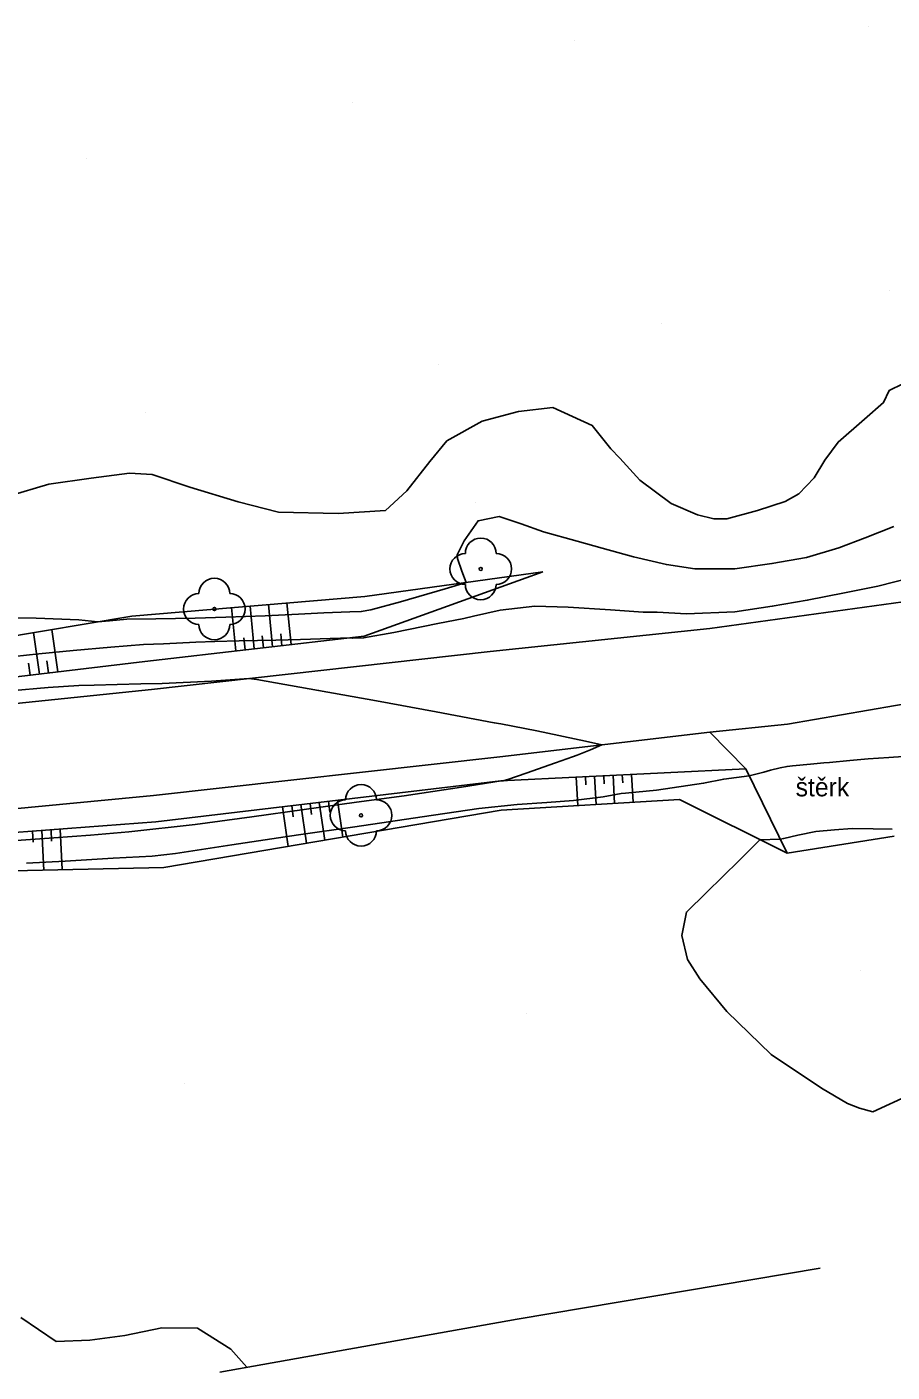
# Model space of a CAD drawing. Extents: x -448957 to -448612, y -1107690 to -1107245.
# Drawn here: x -448841.97 to -448813.9, y -1107413.24 to -1107369.6 of the extents above; entities that cross this region are included whole.
import ezdxf

# ---------------------------------------------------------------- set-up
doc = ezdxf.new("R2010")
doc.units = 0
for name, color, linetype in [('22', 7, 'Continuous'), ('Default', 7, 'Continuous'), ('Vrstva 1', 7, 'Continuous'), ('Vrstva 10', 7, 'Continuous'), ('Vrstva 11', 7, 'Continuous'), ('Vrstva 14', 7, 'Continuous'), ('Vrstva 15', 7, 'Continuous'), ('Vrstva 16', 7, 'Continuous'), ('Vrstva 17', 7, 'Continuous'), ('Vrstva 22', 7, 'Continuous'), ('Vrstva 40', 7, 'Continuous'), ('Vrstva 7', 7, 'Continuous')]:
    doc.layers.add(name, color=color, linetype=linetype)

# ---------------------------------------------------------------- blocks, each defined once
blk = doc.blocks.new('POINT_DISPLAY')
at = {"layer": 'Default'}
blk.add_line((0, 0), (0, 0), dxfattribs=at)
blk = doc.blocks.new('STROM$5')
at = {"layer": '22'}
blk.add_circle((0, 0), 0.5, dxfattribs=at)
for centre, start, end in [((0, 5), 0, 180), ((-5, 0), 90, 270), ((5, 0), 270, 90), ((0, -5), 180, 0)]:
    blk.add_arc(centre, 5, start, end, dxfattribs=at)

msp = doc.modelspace()

# ---------------------------------------------------------------- linework, layer by layer
at = {"layer": 'Vrstva 10'}
for p, q in [((-448819.806, -1107389.115), (-448812.577, -1107388.123)), ((-448826.941, -1107389.864), (-448819.806, -1107389.115)), ((-448837.92, -1107391.094), (-448826.941, -1107389.864)), ((-448845.33, -1107391.868), (-448837.92, -1107391.094)), ((-448817.294, -1107392.217), (-448811.47, -1107391.213)), ((-448826.623, -1107393.28), (-448819.81, -1107392.483)), ((-448819.81, -1107392.483), (-448817.294, -1107392.217)), ((-448837.857, -1107394.533), (-448826.623, -1107393.28)), ((-448845.099, -1107395.225), (-448837.857, -1107394.533))]:
    msp.add_line(p, q, dxfattribs=at)
at = {"layer": 'Vrstva 11'}
for p, q in [((-448819.81, -1107392.483), (-448818.647, -1107393.672)), ((-448818.647, -1107393.672), (-448817.303, -1107396.41)), ((-448817.303, -1107396.41), (-448813.828, -1107395.852))]:
    msp.add_line(p, q, dxfattribs=at)
at = {"layer": 'Vrstva 14'}
for p, q in [((-448831.021, -1107389.369), (-448825.225, -1107387.274)), ((-448831.004, -1107388.073), (-448825.225, -1107387.274)), ((-448838.566, -1107388.715), (-448831.004, -1107388.073)), ((-448845.445, -1107389.871), (-448838.566, -1107388.715)), ((-448838.141, -1107390.183), (-448831.021, -1107389.369)), ((-448845.414, -1107391.056), (-448838.141, -1107390.183)), ((-448826.595, -1107394.055), (-448818.647, -1107393.672)), ((-448837.783, -1107395.389), (-448826.595, -1107394.055)), ((-448826.579, -1107395.014), (-448820.79, -1107394.663)), ((-448820.79, -1107394.663), (-448817.303, -1107396.41)), ((-448837.524, -1107396.869), (-448826.579, -1107395.014)), ((-448845.062, -1107395.942), (-448837.783, -1107395.389)), ((-448845.125, -1107397.033), (-448837.524, -1107396.869))]:
    msp.add_line(p, q, dxfattribs=at)
at = {"layer": 'Vrstva 15'}
for p, q in [((-448835.186, -1107389.845), (-448835.326, -1107388.44)), ((-448834.59, -1107389.777), (-448834.728, -1107388.389)), ((-448833.994, -1107389.709), (-448834.13, -1107388.338)), ((-448833.398, -1107389.641), (-448833.532, -1107388.288)), ((-448841.561, -1107390.594), (-448841.755, -1107389.251)), ((-448840.966, -1107390.522), (-448841.163, -1107389.151)), ((-448834.888, -1107389.811), (-448834.928, -1107389.415)), ((-448834.292, -1107389.743), (-448834.331, -1107389.351)), ((-448833.696, -1107389.675), (-448833.734, -1107389.288)), ((-448841.859, -1107390.629), (-448841.915, -1107390.246)), ((-448841.264, -1107390.558), (-448841.32, -1107390.166)), ((-448823.849, -1107393.923), (-448823.834, -1107394.187)), ((-448823.549, -1107393.908), (-448823.499, -1107394.827)), ((-448823.25, -1107393.894), (-448823.235, -1107394.156)), ((-448822.95, -1107393.879), (-448822.9, -1107394.791)), ((-448822.65, -1107393.865), (-448822.636, -1107394.125)), ((-448822.351, -1107393.85), (-448822.301, -1107394.755)), ((-448824.149, -1107393.937), (-448824.098, -1107394.864)), ((-448832.781, -1107394.793), (-448832.729, -1107395.152)), ((-448832.483, -1107394.757), (-448832.306, -1107395.985)), ((-448832.185, -1107394.721), (-448832.134, -1107395.072)), ((-448831.887, -1107394.686), (-448831.714, -1107395.884)), ((-448833.675, -1107394.899), (-448833.489, -1107396.185)), ((-448833.377, -1107394.864), (-448833.324, -1107395.231)), ((-448833.079, -1107394.828), (-448832.897, -1107396.085)), ((-448841.483, -1107395.67), (-448841.42, -1107396.953)), ((-448841.184, -1107395.647), (-448841.166, -1107396.014)), ((-448840.884, -1107395.625), (-448840.82, -1107396.94)), ((-448841.782, -1107395.693), (-448841.765, -1107396.05))]:
    msp.add_line(p, q, dxfattribs=at)
at = {"layer": 'Vrstva 16'}
for points in [[(-448813.846, -1107385.806), (-448814.768, -1107386.18), (-448815.623, -1107386.497), (-448816.676, -1107386.814), (-448817.798, -1107387.013), (-448819.003, -1107387.181), (-448820.3, -1107387.177), (-448821.22, -1107387.042), (-448822.285, -1107386.788), (-448823.301, -1107386.509), (-448824.114, -1107386.283), (-448825.207, -1107385.977), (-448825.928, -1107385.721), (-448826.64, -1107385.478), (-448827.329, -1107385.621), (-448827.784, -1107386.276), (-448828.013, -1107386.731), (-448827.997, -1107386.85), (-448827.852, -1107387.253), (-448827.718, -1107387.619), (-448828.399, -1107387.832), (-448829.845, -1107388.247), (-448830.81, -1107388.506), (-448831.12, -1107388.566), (-448831.494, -1107388.58), (-448832.329, -1107388.612), (-448833.156, -1107388.654), (-448834.236, -1107388.707), (-448835.515, -1107388.749), (-448836.503, -1107388.776), (-448837.788, -1107388.799), (-448838.728, -1107388.819), (-448839.29, -1107388.867), (-448839.665, -1107388.9), (-448840.287, -1107388.839), (-448841.671, -1107388.786), (-448842.85, -1107388.773)], [(-448813.305, -1107404.233), (-448814.524, -1107404.794), (-448814.959, -1107404.683), (-448815.343, -1107404.526), (-448816.192, -1107404.027), (-448817.821, -1107402.937), (-448819.26, -1107401.541), (-448820.133, -1107400.487), (-448820.54, -1107399.852), (-448820.714, -1107399.079), (-448820.572, -1107398.316), (-448819.921, -1107397.686), (-448818.86, -1107396.644), (-448818.185, -1107395.968), (-448817.526, -1107395.955), (-448817.414, -1107395.928), (-448816.955, -1107395.819), (-448816.376, -1107395.706), (-448815.767, -1107395.645), (-448815.188, -1107395.604), (-448814.509, -1107395.615), (-448813.894, -1107395.624)], [(-448842.163, -1107411.465), (-448841.015, -1107412.25), (-448839.924, -1107412.2), (-448838.786, -1107412.052), (-448837.587, -1107411.81), (-448836.431, -1107411.815), (-448835.355, -1107412.496), (-448834.835, -1107413.085)]]:
    msp.add_lwpolyline(points, dxfattribs=at)
at = {"layer": 'Vrstva 17'}
for points in [[(-448813.55, -1107381.175), (-448813.996, -1107381.396), (-448814.172, -1107381.788), (-448814.791, -1107382.326), (-448815.651, -1107383.066), (-448816.074, -1107383.655), (-448816.42, -1107384.233), (-448816.928, -1107384.743), (-448817.361, -1107384.995), (-448818.269, -1107385.292), (-448819.257, -1107385.563), (-448819.676, -1107385.561), (-448820.21, -1107385.431), (-448821.068, -1107385.064), (-448822.081, -1107384.301), (-448822.734, -1107383.592), (-448823.018, -1107383.287), (-448823.623, -1107382.531), (-448824.905, -1107381.944), (-448826.018, -1107382.08), (-448827.199, -1107382.388), (-448828.343, -1107383.023), (-448828.897, -1107383.703), (-448829.637, -1107384.648), (-448830.338, -1107385.287), (-448831.87, -1107385.381), (-448833.803, -1107385.347), (-448835.108, -1107385.01), (-448836.682, -1107384.534), (-448837.906, -1107384.12), (-448838.643, -1107384.073), (-448839.885, -1107384.236), (-448841.252, -1107384.438), (-448842.561, -1107384.824)], [(-448813.295, -1107387.468), (-448814.359, -1107387.741), (-448815.439, -1107387.957), (-448816.651, -1107388.202), (-448817.787, -1107388.395), (-448818.994, -1107388.575), (-448820.568, -1107388.639), (-448821.523, -1107388.589), (-448821.971, -1107388.582), (-448823.032, -1107388.513), (-448824.407, -1107388.429), (-448825.486, -1107388.388), (-448826.612, -1107388.522), (-448827.475, -1107388.717), (-448827.792, -1107388.789), (-448828.638, -1107388.958), (-448830.066, -1107389.251), (-448831.042, -1107389.423), (-448831.398, -1107389.433), (-448831.471, -1107389.42), (-448832.127, -1107389.44), (-448833.088, -1107389.471), (-448833.893, -1107389.494), (-448835.079, -1107389.519), (-448835.868, -1107389.538), (-448836.488, -1107389.564), (-448837.539, -1107389.609), (-448838.187, -1107389.636), (-448839.241, -1107389.722), (-448840.465, -1107389.829), (-448841.581, -1107389.942), (-448842.777, -1107390.066)], [(-448826.519, -1107394.054), (-448826.479, -1107394.049), (-448826.361, -1107394.011), (-448825.766, -1107393.808), (-448824.814, -1107393.479), (-448824.263, -1107393.285), (-448824.115, -1107393.229), (-448823.678, -1107393.048), (-448823.311, -1107392.893), (-448823.849, -1107392.769), (-448825.427, -1107392.441), (-448826.596, -1107392.213), (-448826.804, -1107392.174), (-448828.685, -1107391.824), (-448830.622, -1107391.465), (-448832.502, -1107391.126), (-448834.51, -1107390.776), (-448834.772, -1107390.741), (-448835.983, -1107390.827), (-448837.582, -1107390.901), (-448838.275, -1107390.909), (-448839.038, -1107390.938), (-448839.789, -1107390.953), (-448840.283, -1107390.964), (-448841.273, -1107391.036), (-448842.505, -1107391.144)], [(-448841.981, -1107396.735), (-448840.722, -1107396.66), (-448839.165, -1107396.567), (-448837.906, -1107396.499), (-448837.145, -1107396.415), (-448835.316, -1107396.136), (-448833.156, -1107395.815), (-448831.324, -1107395.552), (-448829.147, -1107395.231), (-448827.304, -1107394.96), (-448826.064, -1107394.83), (-448825.1, -1107394.762), (-448824.235, -1107394.693), (-448823.271, -1107394.573), (-448822.683, -1107394.475), (-448822.542, -1107394.458), (-448821.545, -1107394.36), (-448820.011, -1107394.138), (-448819.36, -1107394), (-448818.943, -1107393.949), (-448818.535, -1107393.9), (-448818.366, -1107393.857), (-448818.062, -1107393.776), (-448817.837, -1107393.713), (-448817.527, -1107393.642), (-448817.302, -1107393.593), (-448817.123, -1107393.575), (-448816.544, -1107393.52), (-448816.115, -1107393.48), (-448815.925, -1107393.464), (-448815.267, -1107393.402), (-448814.677, -1107393.348), (-448814.004, -1107393.302), (-448813.221, -1107393.245)], [(-448842.31, -1107395.997), (-448841.097, -1107395.909), (-448839.9, -1107395.82), (-448838.656, -1107395.715), (-448836.513, -1107395.473), (-448834.669, -1107395.224), (-448831.277, -1107394.756), (-448829.731, -1107394.544), (-448827.868, -1107394.262), (-448826.577, -1107394.061), (-448826.519, -1107394.054)]]:
    msp.add_lwpolyline(points, dxfattribs=at)
at = {"layer": 'Vrstva 7'}
for p, q in [((-448826.056, -1107411.525), (-448816.229, -1107409.874)), ((-448835.712, -1107413.241), (-448826.056, -1107411.525))]:
    msp.add_line(p, q, dxfattribs=at)

# ---------------------------------------------------------------- block references
at = {"layer": 'Vrstva 1', "xscale": 0.1, "yscale": 0.10000000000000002}
for p in [(-448825.225, -1107387.274), (-448825.225, -1107387.274), (-448831.004, -1107388.073), (-448838.566, -1107388.715), (-448819.806, -1107389.115), (-448831.021, -1107389.369), (-448831.021, -1107389.369), (-448826.941, -1107389.864), (-448838.141, -1107390.183), (-448837.92, -1107391.094), (-448819.81, -1107392.483), (-448819.81, -1107392.483), (-448817.294, -1107392.217), (-448826.623, -1107393.28), (-448818.647, -1107393.672), (-448818.647, -1107393.672), (-448826.595, -1107394.055), (-448837.857, -1107394.533), (-448820.79, -1107394.663), (-448820.79, -1107394.663), (-448826.579, -1107395.014), (-448837.783, -1107395.389), (-448817.303, -1107396.41), (-448817.303, -1107396.41), (-448837.524, -1107396.869), (-448816.229, -1107409.874), (-448826.056, -1107411.525), (-448835.712, -1107413.241)]:
    msp.add_blockref('POINT_DISPLAY', p, dxfattribs=at)
at = {"layer": 'Vrstva 14', "xscale": 0.1, "yscale": 0.10000000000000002}
for p in [(-448814.658, -1107369.599), (-448824.2, -1107370.046), (-448831.409, -1107372.04), (-448840.021, -1107373.865), (-448813.966, -1107378.163), (-448821.385, -1107379.219), (-448828.608, -1107380.566), (-448838.115, -1107382.115), (-448827.401, -1107385.036), (-448819.439, -1107385.38), (-448814.912, -1107400.224), (-448825.768, -1107401.611), (-448836.847, -1107403.882)]:
    msp.add_blockref('POINT_DISPLAY', p, dxfattribs=at)
at = {"layer": 'Vrstva 22', "xscale": 0.1, "yscale": 0.10000000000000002}
for p in [(-448827.243, -1107387.184), (-448835.885, -1107388.485), (-448831.126, -1107395.178)]:
    msp.add_blockref('STROM$5', p, dxfattribs=at)

# ---------------------------------------------------------------- texts
at = {"layer": 'Vrstva 40'}
msp.add_text('štěrk', height=0.6, dxfattribs=at).set_placement((-448817.026, -1107394.562))

doc.saveas('drawing.dxf')
